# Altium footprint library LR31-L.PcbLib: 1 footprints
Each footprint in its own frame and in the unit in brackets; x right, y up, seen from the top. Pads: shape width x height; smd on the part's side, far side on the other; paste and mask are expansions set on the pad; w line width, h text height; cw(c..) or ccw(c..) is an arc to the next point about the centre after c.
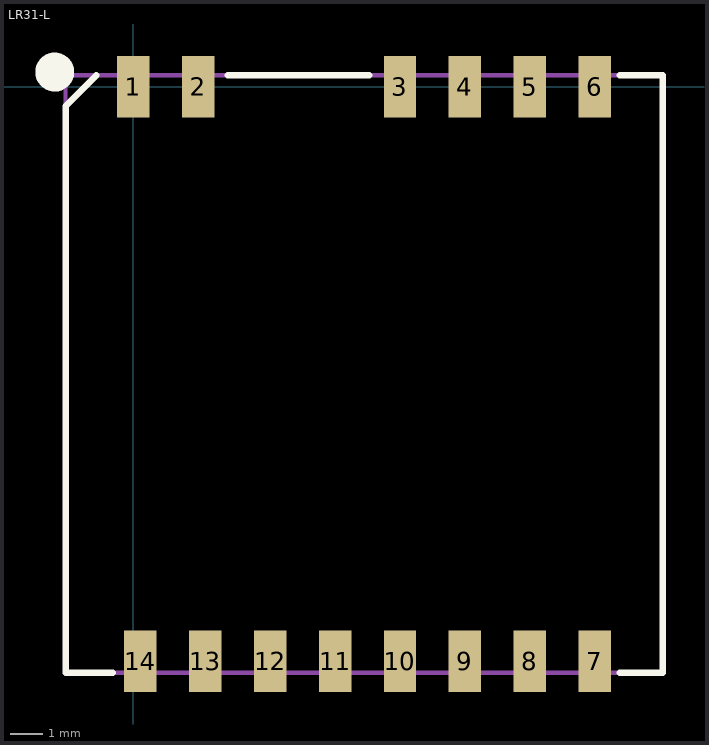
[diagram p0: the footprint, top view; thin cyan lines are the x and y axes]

## LR31-L [mm]
pads (14):
  rect 1x1.9 smd: 1(0,0) 2(2,0) 3(8.22,0) 4(10.22,0) 5(12.22,0) 6(14.22,0) 7(14.22,-17.7) 8(12.22,-17.7) 9(10.22,-17.7) 10(8.22,-17.7) 11(6.22,-17.7) 12(4.22,-17.7) 13(2.22,-17.7) 14(0.22,-17.7)
Top Overlay:
  circle w0.6: c-2.413,0.45 r0.3
  lines w0.2: -1.13,0.35 -2.08,-0.6 -2.08,-18.05 -0.63,-18.05 ; 2.92,0.35 7.27,0.35 ; 14.99,-18.05 16.32,-18.05 16.32,0.35 14.99,0.35
Mechanical 1:
  lines w0.127: -2.08,-18.05 -2.08,0.35 16.32,0.35 16.32,-18.05 -2.08,-18.05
